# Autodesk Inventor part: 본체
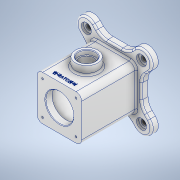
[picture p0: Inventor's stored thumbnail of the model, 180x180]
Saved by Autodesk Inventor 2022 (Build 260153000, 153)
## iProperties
Created: 2022-05
Part Number: 본체
Material: 알루미늄 6061
Document SubType Name: Modeling
Designer: admin
Density: 2.7 g/cm^3
Appearance: 알루미늄 - 평지
Mass: 1076.28 g
Surface Area: 879.964 cm^2
Volume: 398.62 cm^3
Author: admin
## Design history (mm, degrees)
sketch "스케치1" dims "d4" = 140
  geometry: L1 (-122.868, 0)-(107.923, 0) reference; L2 (0, -107.923)-(0, 122.868) reference; L3 (-49, 0)-(-49, 23.544); L4 (-49, 49)-(0, 49); L5 (0, 0)-(-89.897, 89.897); L6 (-49.497, 49.497)-(-25.81, 73.185); L7 (-49.497, 49.497)-(-70, 28.995); L8 (-36.77, 62.225)-(-23.544, 49); L9 (-62.225, 36.77)-(-49, 23.544); L10 (0, 49)-(-23.544, 49); L11 (-62.225, -36.77)-(-49, -23.544); L12 (-36.77, -62.225)-(-23.544, -49); L13 (0, -49)-(-23.544, -49); L14 (-49, 0)-(-49, -23.544); L15 (36.77, -62.225)-(23.544, -49); L16 (62.225, -36.77)-(49, -23.544); L17 (49, 0)-(49, -23.544); L18 (0, -49)-(23.544, -49); L19 (62.225, 36.77)-(49, 23.544); L20 (36.77, 62.225)-(23.544, 49); L21 (0, 49)-(23.544, 49); L22 (49, 0)-(49, 23.544); C1 r 5 at (-49.497, 49.497); C2 r 5 at (-49.497, -49.497); C3 r 5 at (49.497, -49.497); C4 r 5 at (49.497, 49.497); A1 r 18 centre (-49.497, 49.497) between (-36.77, 62.225) and (-62.225, 36.77); A2 r 18 centre (-49.497, -49.497) between (-62.225, -36.77) and (-36.77, -62.225); A3 r 18 centre (49.497, -49.497) between (36.77, -62.225) and (62.225, -36.77); A4 r 18 centre (49.497, 49.497) between (62.225, 36.77) and (36.77, 62.225); 5 further points
  constraints: 40 end point, 8 centre point, 8 point on circle, 7 point on line, 5 coincident, 3 perpendicular, 1 parallel, 1 tangent, 1 vertical, 62 other
  dimensions: "d0" = 49 distance of L4.start L4.end; "d1" = 49 distance of L3.start L4.start; "d2" = 45 deg angle of L2 L5; "d3" = 36 diameter of A1; "d5" = 49 distance between parallel lines of L1 L4; "d6" = 10 diameter of C1; "d9" = 360 deg dimension on point (0, 0) L6.start (derived)
extrude "돌출1" new body sketch "스케치1" distance "d11" = 12; taper "d12" = 0 deg
sketch "스케치2"
  geometry: L1 (-94.496, 0)-(94.496, 0) reference; L2 (0, -94.496)-(0, 94.496) reference; C1 r 5 at (-49.497, 49.497) reference; C2 r 9 at (-49.497, 49.497); C3 r 9 at (49.497, 49.497); C4 r 9 at (-49.497, -49.497); C5 r 9 at (49.497, -49.497); 1 further point
  constraints: 4 centre point, 3 symmetric about line, 1 coincident, 3 other
  dimensions: "d13" = 18 diameter of C2
extrude "돌출2" cut sketch "스케치2" distance "d14" = 4; taper "d15" = 0 deg
sketch "스케치3"
  geometry: L1 (-40, -40)-(40, -40); L2 (40, -40)-(40, 40); L3 (40, 40)-(-40, 40); L4 (-40, 40)-(-40, -40); L5 (-40, -40)-(40, 40); L6 (40, -40)-(-40, 40); 1 further point
  constraints: 12 end point, 2 midpoint, 2 parallel, 1 horizontal, 1 perpendicular
  dimensions: "d16" = 80 distance of L2.end L3.end; "d17" = 80 distance of L1.end L2.end
extrude "돌출3" join sketch "스케치3" distance "d18" = 98; taper "d19" = 0 deg
sketch "스케치4"
  geometry: C1 r 25 at (0, 0); 1 further point
  constraints: 1 centre point, 1 coincident
  dimensions: "d20" = 50 diameter of C1
extrude "돌출4" cut sketch "스케치4" extent not by distance; stored distance "d21" = 0; taper "d22" = 0 deg
node "작업 평면1"
sketch "스케치5"
  geometry: C1 r 35 at (0, 0); 1 further point
  constraints: 1 centre point, 1 coincident
  dimensions: "d24" = 70 diameter of C1
extrude "돌출5" cut sketch "스케치5" distance "d25" = 86; taper "d26" = 0 deg
sketch "스케치6"
  geometry: L1 (63.544, 0)-(16.456, 0) reference; L2 (0, 0)-(0, -98) reference; C1 r 20 at (40, -49); 1 further point
  constraints: 1 centre point
  dimensions: "d27" = 40 diameter of C1; "d28" = 49 distance from line of L1 C1.centre; "d29" = 40 distance from line of C1.centre L2
extrude "돌출6" join sketch "스케치6" distance "d30" = 15; taper "d31" = 0 deg
sketch "스케치7"
  geometry: L1 (0, 83)-(0, -71) reference; L2 (23.544, 49)-(-23.544, 49) reference; C1 r 12.5 at (0, 0); 1 further point
  constraints: 1 centre point, 1 point on line
  dimensions: "d32" = 25 diameter of C1; "d33" = 49 distance from line of L2 C1.centre
extrude "돌출7" cut sketch "스케치7" stored distance "d34" = 15; taper "d35" = 0 deg
sketch "스케치8"
  geometry: L1 (23.544, 49)-(-23.544, 49) reference; L2 (-40, 49)-(-40, -49) reference; C1 r 15 at (0, 0); 1 further point
  constraints: 1 centre point
  dimensions: "d36" = 30 diameter of C1; "d37" = 49 distance from line of L1 C1.centre; "d38" = 40 distance from line of L2 C1.centre
extrude "돌출8" cut sketch "스케치8" distance "d39" = 8; taper "d40" = 0 deg
sketch "스케치9"
  geometry: L1 (80, -98)-(0, -98) reference; L2 (80, 0)-(80, -98) reference; 2 further points
  constraints: 1 other
  dimensions: "d41" = 10 distance from line of L1 point (40, -88); "d42" = 40 distance from line of L2 point (40, -88)
feature "엠보싱1" sketch "스케치9" dims "d43" = 0.5, "d44" = 0
sketch "스케치10"
  geometry: L1 (-30, -30)-(30, -30); L2 (30, -30)-(30, 30); L3 (30, 30)-(-30, 30); L4 (-30, 30)-(-30, -30); L5 (-30, -30)-(30, 30); L6 (30, -30)-(-30, 30); 5 further points
  constraints: 12 end point, 4 coincident, 2 midpoint, 2 parallel, 1 horizontal, 1 perpendicular
  dimensions: "d45" = 60 distance of L3.end L2.end; "d46" = 60 distance of L2.end L1.end
hole "구멍1" sketch "스케치10" at (-30, 30), (30, 30), (30, -30), (-30, -30) diameter "d47" = 3.242; stored, may be unused: countersink angle "d51" = 90 deg, drill point angle "d53" = 118 deg; dims "d48" = 8, "d49" = 4, "d50" = 2, "d52" = 10
fillet "모깎기1" dims "d54" = 10
fillet "모깎기2" dims "d55" = 25
fillet "모깎기3" dims "d56" = 3
chamfer "모따기1" distance "d57" = 1; stored, may be unused: second distance "d58" = 2, angle "d59" = 45 deg
fillet "모깎기4" dims "d60" = 3
sketch "스케치11"
  geometry: C1 r 1.621 at (-30, 30) reference; C2 r 1.621 at (30, 30) reference; C3 r 1.621 at (30, -30) reference; C4 r 1.621 at (-30, -30) reference; 5 further points
  constraints: 4 coincident
hole "구멍2" sketch "스케치11" at (-30, 30), (30, 30), (30, -30), (-30, -30) diameter "d61" = 3.242; stored, may be unused: countersink angle "d65" = 90 deg, drill point angle "d67" = 118 deg; dims "d62" = 8, "d63" = 4, "d64" = 2, "d66" = 10
node "솔리드1"
feature "A9D066F2-1C7D-4E18-AEED-F7BC21143FA4" dims "d47" = 3.242, "d48" = 8, "d49" = 4, "d50" = 2, "d51" = 90 deg, "d52" = 10, "d53" = 118 deg
other parameters: "d23" = -12
